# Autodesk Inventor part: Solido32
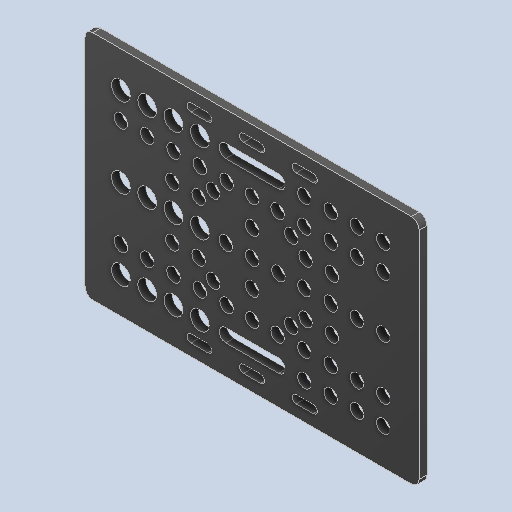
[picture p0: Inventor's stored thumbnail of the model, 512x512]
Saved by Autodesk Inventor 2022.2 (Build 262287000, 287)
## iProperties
Created: 2024-10
Part Number: Solido32
Material: Alluminio 6061
Document SubType Name: Modeling
Designer: 18907419
Density: 2.7 g/cm^3
Appearance: Default
Author: 18907419
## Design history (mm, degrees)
feature "Solido32"
node "Solido1"
